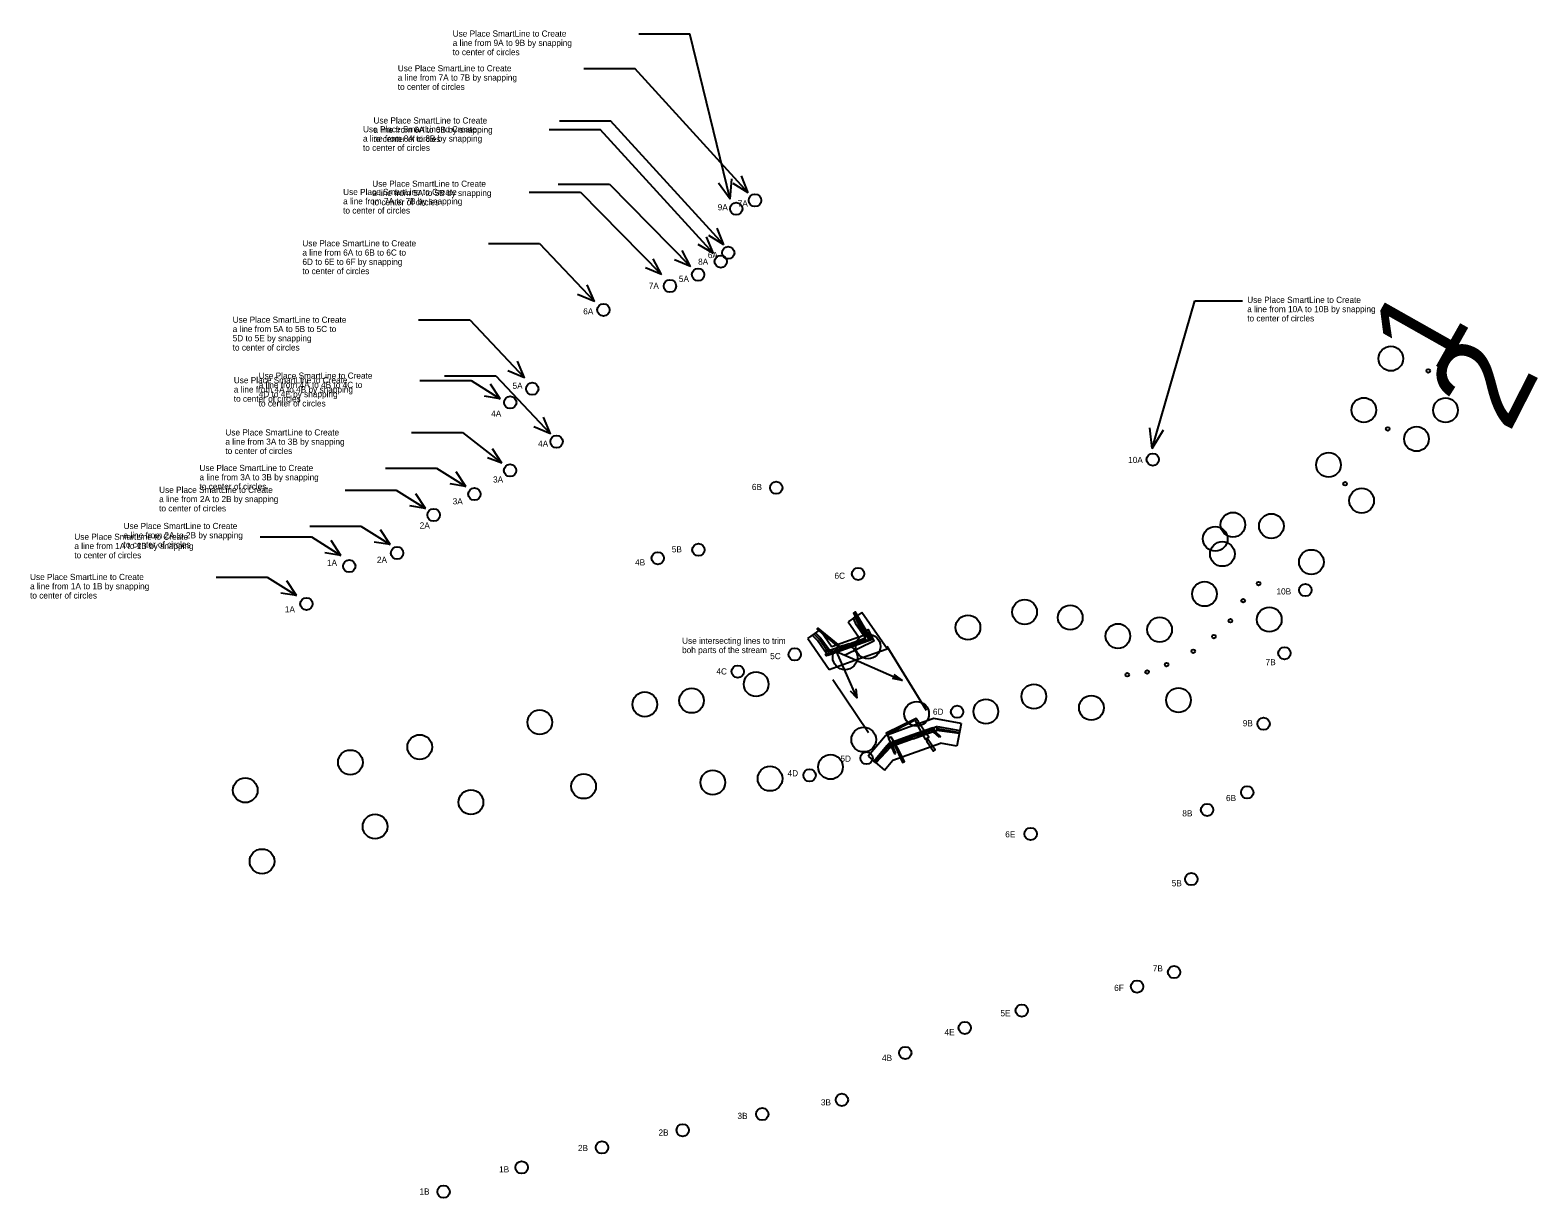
# Model space of a CAD drawing. Extents: x 74477 to 81269, y 49330 to 50934.
# Drawn here: x 74477 to 75699, y 49330 to 50276 of the extents above; entities that cross this region are included whole.
import ezdxf

# ---------------------------------------------------------------- set-up
doc = ezdxf.new("R2010")
doc.units = 0
for name, color, linetype in [('1', 7, 'Continuous'), ('13', 7, 'Continuous'), ('2', 7, 'Continuous'), ('3', 7, 'Continuous'), ('4', 7, 'Continuous'), ('5', 7, 'Continuous'), ('6', 7, 'Continuous')]:
    doc.layers.add(name, color=color, linetype=linetype)

msp = doc.modelspace()

# ---------------------------------------------------------------- linework, layer by layer
at = {"layer": '1'}
for points in [[(75156.2, 49784.7), (75157.2, 49785.3), (75155.7, 49787.9), (75155.5, 49787.9), (75145.7, 49804.9), (75144.2, 49803.9), (75149.4, 49794.7), (75153.4, 49787.8), (75154.9, 49786.9)], [(75134.7, 49773.5), (75133.2, 49775), (75131, 49777.3), (75114.7, 49791.2), (75115.2, 49791.8), (75131.5, 49778.5), (75134, 49776.2), (75135.4, 49774.1)], [(75154.6, 49789.8), (75156.2, 49790.5), (75160.6, 49781.3), (75137.4, 49769.7), (75137, 49770.4)], [(75194, 49717.1), (75195.4, 49714.8), (75195.4, 49714.3), (75202.2, 49701.8), (75205.2, 49703.5), (75197, 49715.4), (75196.8, 49715.8), (75194.9, 49718.5), (75170.8, 49706.6), (75172.5, 49702.9), (75172.6, 49702.4), (75174.6, 49698.2), (75177.1, 49699.3), (75174.8, 49703.4), (75173.5, 49702.8), (75173.2, 49703.1), (75171.8, 49705.9), (75193.6, 49717.2)], [(75176.7, 49698.8), (75183.9, 49682.8), (75185.6, 49683.7), (75180.3, 49693.8), (75177.2, 49698.8)], [(75177.2, 49698.8), (75176.7, 49698.8)], [(75203.1, 49701.9), (75203.6, 49700), (75209, 49692), (75210.3, 49693.2), (75204.8, 49701.2), (75203.9, 49702.2)], [(75203.9, 49702.2), (75203.1, 49701.9)]]:
    msp.add_lwpolyline(points, dxfattribs=at)
at = {"layer": '13'}
for centre in [(75579.7, 50010.1), (75557.8, 49968.4), (75624, 49968.3), (75600.5, 49945), (75529.2, 49924), (75556, 49895), (75451.7, 49875.5), (75482.9, 49874.4), (75437.4, 49864.1), (75443.2, 49851.8), (75515.3, 49845.3), (75428.7, 49819.4), (75282.9, 49804.8), (75237, 49792.3), (75319.9, 49800.3), (75481.2, 49798.7), (75358.5, 49785.3), (75392.3, 49790.5), (75137.4, 49768), (75156, 49776.9), (75065.3, 49746.3), (75013, 49733), (75290.4, 49736.4), (75407.6, 49733.4), (74975.1, 49730), (75195.4, 49722.3), (75251.5, 49724.2), (75337, 49727.2), (74890, 49715.5), (74792.7, 49695.4), (75152.5, 49701.4), (74736.5, 49683), (75125.6, 49679.3), (74651.3, 49660.4), (74925.5, 49663.6), (75030.2, 49666.7), (75076.6, 49669.8), (74834.2, 49650.7), (74756.5, 49631), (74664.9, 49602.8)]:
    msp.add_circle(centre, 10, dxfattribs=at)
at = {"layer": '2'}
for p, q in [((75151, 49804.5), (75140, 49796.8)), ((75171.5, 49775), (75151, 49804.5)), ((75107.1, 49783.4), (75117.1, 49790.4)), ((75117.1, 49790.4), (75126.8, 49776.5)), ((75140, 49796.8), (75148.6, 49784.3)), ((75144.1, 49799.7), (75146.9, 49801.6)), ((75146.6, 49794.2), (75144.1, 49799.7)), ((75145.5, 49800.6), (75148, 49795.2)), ((75153.1, 49784.7), (75146.6, 49794.2)), ((75146.9, 49801.6), (75149.4, 49796.2)), ((75149, 49793.7), (75147.6, 49792.7)), ((75148, 49795.2), (75154.8, 49785.3)), ((75149.5, 49792.9), (75148.1, 49791.9)), ((75149.3, 49793.3), (75148.6, 49792.8)), ((75150.1, 49792.1), (75148.7, 49791.1)), ((75149.8, 49792.5), (75149.1, 49792)), ((75150.7, 49791.3), (75149.2, 49790.3)), ((75149.4, 49796.2), (75156.5, 49785.9)), ((75150.4, 49791.7), (75149.7, 49791.2)), ((75107.1, 49783.4), (75124.6, 49758.2)), ((75115, 49781.8), (75110.8, 49786)), ((75116.5, 49782.8), (75112.2, 49787)), ((75113.5, 49787.9), (75117.7, 49783.7)), ((75121, 49773.1), (75115, 49781.8)), ((75122.7, 49773.8), (75116.5, 49782.8)), ((75118.2, 49783), (75116.9, 49782.1)), ((75117.2, 49781.7), (75117.8, 49782.2)), ((75118.8, 49782.2), (75117.5, 49781.3)), ((75117.7, 49783.7), (75124.4, 49774.3)), ((75117.7, 49780.9), (75118.4, 49781.3)), ((75119.3, 49781.4), (75118, 49780.5)), ((75118.3, 49780.1), (75118.9, 49780.5)), ((75119.9, 49780.6), (75118.6, 49779.7)), ((75140.6, 49779.1), (75124.9, 49773.5)), ((75148.6, 49784.3), (75126.8, 49776.5)), ((75140.6, 49779.1), (75153.4, 49783.7)), ((75154, 49782.3), (75141.1, 49777.7)), ((75141.4, 49777), (75159.6, 49783.5)), ((75141.6, 49776.2), (75158.9, 49782.5)), ((75143.2, 49778.4), (75142.7, 49779.9)), ((75143.7, 49778.6), (75143.4, 49779.3)), ((75144.1, 49778.7), (75143.6, 49780.2)), ((75144.6, 49778.9), (75144.3, 49779.6)), ((75145.1, 49779.1), (75144.5, 49780.6)), ((75145.5, 49779.2), (75145.3, 49780)), ((75146, 49779.4), (75145.5, 49780.9)), ((75156.5, 49785.9), (75153.1, 49784.7)), ((75153.4, 49783.7), (75154, 49782.3)), ((75124.4, 49774.3), (75121, 49773.1)), ((75121.8, 49769.9), (75141.4, 49777)), ((75123.4, 49769.7), (75141.6, 49776.2)), ((75124.6, 49758.2), (75145.4, 49765.7)), ((75124.9, 49773.5), (75125.8, 49772.2)), ((75125.8, 49772.2), (75141.1, 49777.7)), ((75133.8, 49775), (75133.3, 49776.5)), ((75134.3, 49775.2), (75134, 49775.9)), ((75134.8, 49775.4), (75134.2, 49776.8)), ((75135.2, 49775.5), (75135, 49776.3)), ((75135.7, 49775.7), (75135.2, 49777.2)), ((75136.2, 49775.9), (75135.9, 49776.6)), ((75136.6, 49776.1), (75136.1, 49777.5)), ((75138.6, 49775.2), (75138.2, 49775)), ((75145.4, 49765.7), (75171.5, 49775)), ((75209.3, 49718.6), (75189.2, 49711.4)), ((75231.4, 49714.6), (75209.3, 49718.6)), ((75170.1, 49704.6), (75156, 49687.9)), ((75189.2, 49711.4), (75170.1, 49704.6)), ((75191.6, 49704.9), (75172.9, 49698.2)), ((75208.5, 49711), (75191.6, 49704.9)), ((75210.1, 49710.8), (75191.8, 49704.2)), ((75208, 49709.2), (75192.1, 49703.5)), ((75192.6, 49702.1), (75208.8, 49708)), ((75194.6, 49706), (75195, 49706.2)), ((75195.8, 49704.8), (75196.3, 49703.5)), ((75196.2, 49705), (75196.5, 49704.3)), ((75196.7, 49705.2), (75197.2, 49703.8)), ((75197.2, 49705.3), (75197.4, 49704.7)), ((75197.7, 49705.5), (75198.2, 49704.1)), ((75198.1, 49705.7), (75198.4, 49705)), ((75198.6, 49705.9), (75199.1, 49704.5)), ((75209.4, 49709.7), (75208, 49709.2)), ((75209.3, 49707.3), (75208, 49709.2)), ((75208, 49709.2), (75209.3, 49707.3)), ((75208.8, 49708), (75208, 49709.2)), ((75209.7, 49707.5), (75208.4, 49709.4)), ((75208.5, 49711), (75211.6, 49712.1)), ((75208.5, 49711), (75209.4, 49709.7)), ((75209.9, 49707.7), (75208.7, 49709.5)), ((75213.9, 49703.2), (75209.3, 49707.3)), ((75210.5, 49708.1), (75209.4, 49709.7)), ((75213.9, 49703.2), (75209.7, 49707.5)), ((75214.1, 49703.4), (75209.9, 49707.7)), ((75211.5, 49708.8), (75210.5, 49708.1)), ((75210.5, 49708.1), (75214.6, 49703.9)), ((75212.1, 49712), (75211.5, 49708.8)), ((75211.6, 49712.1), (75212.1, 49712)), ((75211.6, 49708.8), (75212.2, 49712)), ((75224.1, 49707.2), (75211.6, 49708.8)), ((75212, 49710.5), (75224.3, 49708.3)), ((75212.2, 49712), (75224.5, 49709.8)), ((75212.5, 49710.4), (75212.7, 49711.9)), ((75219.3, 49707.8), (75219.6, 49709.2)), ((75220.1, 49709.1), (75220, 49708.6)), ((75220.3, 49707.7), (75220.6, 49709)), ((75221.1, 49708.9), (75221, 49708.5)), ((75221.3, 49707.6), (75221.6, 49708.8)), ((75222.1, 49708.7), (75222, 49708.4)), ((75222.3, 49707.4), (75222.5, 49708.6)), ((75229.9, 49706.5), (75224.1, 49707.2)), ((75224.3, 49708.3), (75230.1, 49707.3)), ((75224.5, 49709.8), (75230.4, 49708.7)), ((75231.4, 49714.6), (75228.1, 49696.2)), ((75164.4, 49688.5), (75171.5, 49696.9)), ((75165.5, 49687.6), (75172.6, 49696)), ((75173.9, 49694.9), (75166.4, 49686.8)), ((75172.3, 49695.6), (75171.2, 49696.5)), ((75171.5, 49696.9), (75173.9, 49694.9)), ((75172.5, 49698.1), (75171.6, 49697)), ((75171.6, 49697), (75174.1, 49694.9)), ((75191.8, 49704.2), (75172.3, 49697.2)), ((75172.9, 49698.2), (75172.5, 49698.1)), ((75172.9, 49698.2), (75173.8, 49697)), ((75173.8, 49697), (75175.2, 49697.5)), ((75175, 49695.2), (75173.8, 49697)), ((75174.1, 49694.9), (75175, 49695.2)), ((75175.7, 49695.6), (75174.5, 49697.2)), ((75175.9, 49695.8), (75174.8, 49697.3)), ((75175, 49695.2), (75177.5, 49689.9)), ((75175.2, 49697.5), (75176.2, 49696)), ((75175.6, 49697.6), (75192.1, 49703.5)), ((75176.1, 49696.2), (75175.6, 49697.6)), ((75176.2, 49696), (75175.7, 49697.6)), ((75178.2, 49690.2), (75175.7, 49695.6)), ((75178.4, 49690.3), (75175.9, 49695.8)), ((75192.6, 49702.1), (75176.1, 49696.2)), ((75176.2, 49684.7), (75214.8, 49698.6)), ((75178.4, 49690.3), (75176.2, 49696)), ((75185, 49701), (75185.5, 49699.6)), ((75185.5, 49701.1), (75185.7, 49700.4)), ((75185.9, 49701.3), (75186.4, 49699.9)), ((75186.4, 49701.5), (75186.6, 49700.8)), ((75186.9, 49701.6), (75187.4, 49700.3)), ((75187.3, 49701.8), (75187.6, 49701.1)), ((75187.8, 49702), (75188.3, 49700.6)), ((75214.6, 49703.9), (75213.9, 49703.2)), ((75228.1, 49696.2), (75214.8, 49698.6)), ((75156, 49687.9), (75169.3, 49676.6)), ((75160.6, 49684), (75164.4, 49688.5)), ((75162.3, 49682.5), (75160.6, 49684)), ((75161.7, 49683), (75165.5, 49687.6)), ((75166.4, 49686.8), (75162.3, 49682.5)), ((75166.2, 49688.3), (75167.1, 49687.6)), ((75166.5, 49688.7), (75166.8, 49688.5)), ((75166.8, 49689.1), (75167.8, 49688.3)), ((75167.2, 49689.5), (75167.5, 49689.2)), ((75167.5, 49689.8), (75168.4, 49689)), ((75167.8, 49690.2), (75168.1, 49689.9)), ((75168.1, 49690.6), (75169.1, 49689.8)), ((75169.3, 49676.6), (75176.2, 49684.7)), ((75177.5, 49689.9), (75178.4, 49690.3))]:
    msp.add_line(p, q, dxfattribs=at)
for points in [[(75158.9, 49782.5), (75156.6, 49785.8), (75153.2, 49784.5), (75153.4, 49783.7)], [(75154.9, 49785.2), (75156.3, 49783.1), (75158, 49783.7)], [(75158.9, 49782.5), (75159.9, 49782.8), (75159, 49784.1), (75158, 49783.7), (75158.9, 49782.5)], [(75123.4, 49769.7), (75121.1, 49773), (75124.4, 49774.2), (75124.9, 49773.5)], [(75123.4, 49769.7), (75122.4, 49769.4), (75121.5, 49770.6), (75122.5, 49771), (75123.4, 49769.7)], [(75122.5, 49771), (75124.2, 49771.6), (75122.8, 49773.6)]]:
    msp.add_lwpolyline(points, dxfattribs=at)
at = {"layer": '3'}
for p, q in [((75130.5, 49772.8), (75121.3, 49772.8)), ((75147.1, 49735), (75130.5, 49772.8)), ((75130.5, 49772.8), (75183.9, 49749.2)), ((75203.4, 49724.9), (75171.6, 49776.8)), ((75183.9, 49749.2), (75177.2, 49754.2)), ((75156.3, 49706.9), (75127.4, 49749.8)), ((75147.1, 49735), (75146.4, 49742.6)), ((75183.9, 49749.2), (75175.7, 49750.8)), ((75147.1, 49735), (75141.9, 49740.6))]:
    msp.add_line(p, q, dxfattribs=at)
at = {"layer": '4'}
for centre in [(75610, 50000.1), (75577.2, 49953.1), (75542.6, 49908.7), (75472.5, 49827.8), (75460, 49814), (75449.7, 49797.7), (75436.3, 49784.9), (75419.6, 49773), (75366.1, 49754), (75382.1, 49756.2), (75398, 49762.2)]:
    msp.add_circle(centre, 1.5, dxfattribs=at)
at = {"layer": '5'}
for p, q in [((74970.2, 50273.2), (75011.7, 50273.2)), ((75044.3, 50139.3), (75011.7, 50273.2)), ((74897.5, 50195.7), (74939, 50195.7)), ((75030.7, 50095.1), (74939, 50195.7)), ((74881.4, 50144.9), (74922.9, 50144.9)), ((74922.9, 50144.9), (74988.6, 50078.1)), ((75044.3, 50139.3), (75034.7, 50152.2)), ((75044.3, 50139.3), (75045.6, 50155.6)), ((75030.7, 50095.1), (75025.2, 50108.7)), ((74848.4, 50103.3), (74889.8, 50103.3)), ((74889.8, 50103.3), (74934.2, 50056.3)), ((75030.7, 50095.1), (75018.4, 50102.6)), ((74988.6, 50078.1), (74975.6, 50083.5)), ((74988.6, 50078.1), (74981.8, 50091)), ((74934.2, 50056.3), (74920.6, 50062)), ((74934.2, 50056.3), (74928.5, 50069.9)), ((75386.4, 49937.2), (75420.8, 50056.8)), ((75420.8, 50056.8), (75459.6, 50056.8)), ((74791.8, 50041.4), (74833.3, 50041.4)), ((74833.3, 50041.4), (74877.7, 49994.5)), ((74877.7, 49994.5), (74864.1, 50000.2)), ((74877.7, 49994.5), (74872, 50008.1)), ((74792.8, 49992.4), (74834.3, 49992.4)), ((74834.3, 49992.4), (74858, 49977.6)), ((74858, 49977.6), (74850.1, 49989.5)), ((74858, 49977.6), (74845.2, 49979.6)), ((75386.4, 49937.2), (75384.5, 49953.9)), ((75386.4, 49937.2), (75395.5, 49952.5)), ((74764.9, 49921.3), (74806.4, 49921.3)), ((74806.4, 49921.3), (74830.1, 49906.5)), ((74830.1, 49906.5), (74822.2, 49918.4)), ((74830.1, 49906.5), (74817.3, 49908.5)), ((74703.5, 49874.3), (74745, 49874.3)), ((74745, 49874.3), (74768.7, 49859.4)), ((74768.7, 49859.4), (74760.8, 49871.3)), ((74768.7, 49859.4), (74755.8, 49861.4)), ((74627.6, 49832.9), (74669.1, 49832.9)), ((74669.1, 49832.9), (74692.8, 49818.1)), ((74692.8, 49818.1), (74684.9, 49830)), ((74692.8, 49818.1), (74680, 49820.1))]:
    msp.add_line(p, q, dxfattribs=at)
for centre in [(75049.2, 50131.5), (75036.7, 50088.7), (74995.5, 50068.9), (74941.6, 50049.5), (74883.9, 49985.6), (74866, 49974.6), (75386.8, 49928.3), (74837, 49900.3), (75081.6, 49905.5), (74774.4, 49852.6), (75018.6, 49855.2), (75148, 49835.7), (75510.4, 49822.6), (74700.9, 49811.4), (75096.6, 49770.5), (75228.2, 49724), (75476.5, 49714.3), (75154.8, 49686.5), (75430.8, 49644.5), (75287.8, 49625), (75404, 49513.1), (75374, 49501.3), (75280.6, 49481.9), (75186.2, 49447.6), (75070.3, 49398.1), (74940.4, 49371), (74812, 49335.2)]:
    msp.add_circle(centre, 5, dxfattribs=at)
at = {"layer": '6'}
for p, q in [((74925.6, 50245.1), (74967.1, 50245.1)), ((75058.8, 50144.5), (74967.1, 50245.1)), ((74905.9, 50202.8), (74947.4, 50202.8)), ((75039.1, 50102.2), (74947.4, 50202.8)), ((75058.8, 50144.5), (75053.4, 50158.1)), ((74904.9, 50151.5), (74946.4, 50151.5)), ((74946.4, 50151.5), (75012.1, 50084.8)), ((75058.8, 50144.5), (75046.6, 50152)), ((75039.1, 50102.2), (75026.9, 50109.7)), ((75039.1, 50102.2), (75033.7, 50115.8)), ((75012.1, 50084.8), (75005.3, 50097.7)), ((75012.1, 50084.8), (74999.2, 50090.2)), ((74812.9, 49996.1), (74854.4, 49996.1)), ((74854.4, 49996.1), (74898.8, 49949.1)), ((74898.8, 49949.1), (74893.1, 49962.7)), ((74785.9, 49950.1), (74827.4, 49950.1)), ((74827.4, 49950.1), (74859.3, 49925.3)), ((74898.8, 49949.1), (74885.2, 49954.8)), ((74859.3, 49925.3), (74851.6, 49936.9)), ((74859.3, 49925.3), (74847.7, 49929.7)), ((74732.2, 49903.6), (74773.7, 49903.6)), ((74773.7, 49903.6), (74797.4, 49888.7)), ((74797.4, 49888.7), (74789.5, 49900.6)), ((74797.4, 49888.7), (74784.6, 49890.7)), ((74663.5, 49865.6), (74705, 49865.6)), ((74705, 49865.6), (74728.7, 49850.7)), ((74728.7, 49850.7), (74715.9, 49852.7)), ((74728.7, 49850.7), (74720.8, 49862.6))]:
    msp.add_line(p, q, dxfattribs=at)
for centre in [(75064.4, 50138.3), (75042.7, 50095.8), (75018.3, 50078.1), (74903.6, 49942.8), (74865.9, 49919.5), (74804, 49883.4), (74985.6, 49848.4), (74735.6, 49842), (75493.5, 49771.4), (75050.4, 49756.5), (75108.6, 49672.5), (75463.3, 49658.7), (75418, 49588.4), (75234.4, 49467.9), (75134.8, 49409.6), (75005.8, 49385), (74875.3, 49354.9)]:
    msp.add_circle(centre, 5, dxfattribs=at)

# ---------------------------------------------------------------- texts
at = {"layer": '13'}
for s, height, rotation, p in [('1', 68.9, 60.5546, (75619.4, 49994.4)), ('2', 76, 63.0543, (75675.5, 49948.6))]:
    msp.add_text(s, height=height, rotation=rotation, dxfattribs=at).set_placement(p)
at = {"layer": '3'}
for s, p in [('Use intersecting lines to trim', (75005.3, 49779)), ('boh parts of the stream', (75005.3, 49771.5))]:
    msp.add_text(s, height=5, dxfattribs=at).set_placement(p)
at = {"layer": '5'}
for s, p in [('a line from 9A to 9B by snapping', (74819.4, 50263.4)), ('Use Place SmartLine to Create', (74819.4, 50270.9)), ('to center of circles', (74819.4, 50255.9)), ('Use Place SmartLine to Create', (74746.7, 50193.4)), ('to center of circles', (74746.7, 50178.4)), ('a line from 8A to 8B by snapping', (74746.7, 50185.9)), ('Use Place SmartLine to Create', (74730.6, 50142.6)), ('to center of circles', (74730.6, 50127.6)), ('a line from 7A to 7B by snapping', (74730.6, 50135.1)), ('9A', (75034.2, 50130.2)), ('a line from 6A to 6B to 6C to', (74697.6, 50093.5)), ('Use Place SmartLine to Create', (74697.6, 50101)), ('to center of circles', (74697.6, 50078.5)), ('6D to 6E to 6F by snapping', (74697.6, 50086)), ('8A', (75018.3, 50086.1)), ('7A', (74978.3, 50066.5)), ('Use Place SmartLine to Create', (75463.3, 50055.2)), ('6A', (74925.2, 50045.9)), ('a line from 10A to 10B by snapping', (75463.3, 50047.7)), ('a line from 5A to 5B to 5C to', (74641.1, 50031.6)), ('Use Place SmartLine to Create', (74641.1, 50039.1)), ('to center of circles', (75463.3, 50040.2)), ('5D to 5E by snapping', (74641.1, 50024.1)), ('to center of circles', (74641.1, 50016.6)), ('a line from 4A to 4B by snapping', (74642, 49982.6)), ('Use Place SmartLine to Create', (74642, 49990.1)), ('5A', (74867.9, 49985.6)), ('to center of circles', (74642, 49975.1)), ('4A', (74850.6, 49963)), ('10A', (75366.8, 49925.5)), ('a line from 3A to 3B by snapping', (74614.2, 49911.5)), ('Use Place SmartLine to Create', (74614.2, 49919)), ('to center of circles', (74614.2, 49904)), ('6B', (75061.9, 49903.6)), ('3A', (74819.4, 49892)), ('Use Place SmartLine to Create', (74552.7, 49872)), ('a line from 2A to 2B by snapping', (74552.7, 49864.5)), ('to center of circles', (74552.7, 49857)), ('5B', (74997, 49853.1)), ('2A', (74758, 49844.6)), ('a line from 1A to 1B by snapping', (74476.9, 49823.2)), ('Use Place SmartLine to Create', (74476.9, 49830.7)), ('6C', (75128.8, 49831.7)), ('to center of circles', (74476.9, 49815.7)), ('10B', (75487, 49819)), ('1A', (74683.4, 49804.5)), ('5C', (75076.7, 49766.6)), ('6D', (75208.6, 49721.5)), ('9B', (75459.7, 49712.2)), ('5D', (75133.6, 49683.5)), ('8B', (75410.7, 49639.2)), ('6E', (75267.2, 49622.2)), ('7B', (75386.8, 49513.6)), ('6F', (75355.5, 49497.8)), ('5E', (75263.3, 49477.3)), ('4B', (75167.3, 49441.1)), ('3B', (75050.2, 49394.1)), ('2B', (74920.9, 49368.1)), ('1B', (74792.5, 49332.8))]:
    msp.add_text(s, height=5, dxfattribs=at).set_placement(p)
at = {"layer": '6'}
for s, p in [('Use Place SmartLine to Create', (74774.9, 50242.8)), ('to center of circles', (74774.9, 50227.8)), ('a line from 7A to 7B by snapping', (74774.9, 50235.3)), ('Use Place SmartLine to Create', (74755.2, 50200.5)), ('a line from 6A to 6B by snapping', (74755.2, 50193)), ('to center of circles', (74755.2, 50185.5)), ('a line from 5A to 5B by snapping', (74754.2, 50141.8)), ('Use Place SmartLine to Create', (74754.2, 50149.3)), ('to center of circles', (74754.2, 50134.3)), ('7A', (75050.4, 50133.3)), ('6A', (75026.2, 50091.5)), ('5A', (75002.7, 50072.2)), ('Use Place SmartLine to Create', (74662.2, 49993.8)), ('a line from 4A to 4B to 4C to', (74662.2, 49986.3)), ('4D to 4E by snapping', (74662.2, 49978.8)), ('to center of circles', (74662.2, 49971.3)), ('Use Place SmartLine to Create', (74635.2, 49947.8)), ('to center of circles', (74635.2, 49932.8)), ('a line from 3A to 3B by snapping', (74635.2, 49940.3)), ('4A', (74888.6, 49938.7)), ('3A', (74852.1, 49909.7)), ('Use Place SmartLine to Create', (74581.5, 49901.3)), ('to center of circles', (74581.5, 49886.3)), ('a line from 2A to 2B by snapping', (74581.5, 49893.8)), ('2A', (74792.7, 49872.4)), ('Use Place SmartLine to Create', (74512.8, 49863.3)), ('to center of circles', (74512.8, 49848.3)), ('a line from 1A to 1B by snapping', (74512.8, 49855.8)), ('1A', (74717.5, 49842.2)), ('4B', (74967.2, 49842.5)), ('7B', (75478.2, 49761.7)), ('4C', (75033.1, 49754.2)), ('4D', (75090.8, 49671.7)), ('6B', (75446.1, 49651.6)), ('5B', (75402.1, 49582.6)), ('4E', (75218, 49461.9)), ('3B', (75117.8, 49405.1)), ('2B', (74986.2, 49380.6)), ('1B', (74857, 49350.8))]:
    msp.add_text(s, height=5, dxfattribs=at).set_placement(p)

doc.saveas('drawing.dxf')
